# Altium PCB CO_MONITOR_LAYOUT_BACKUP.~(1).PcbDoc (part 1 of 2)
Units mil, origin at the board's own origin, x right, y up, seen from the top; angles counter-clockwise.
Board outline 3010 x 4260 mil, 2 copper layers (Top Layer, Bottom Layer), stack 62 mil thick; 120 components, 0 nets, 435 pads, 123 vias.
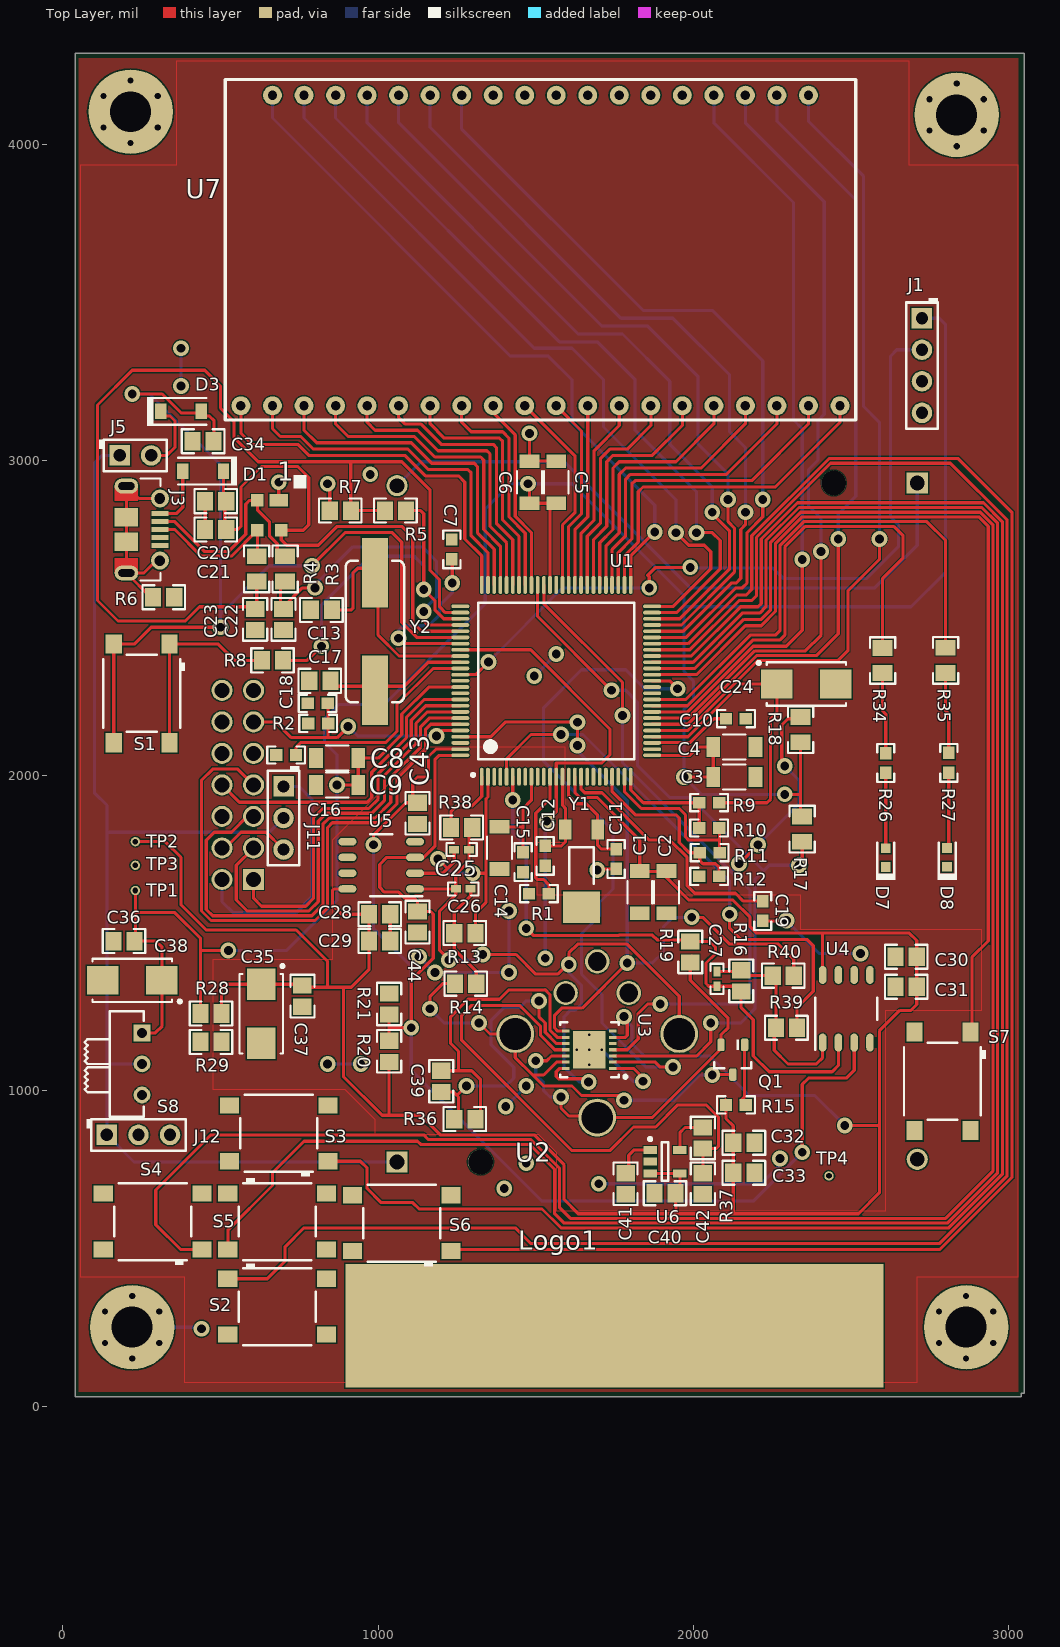
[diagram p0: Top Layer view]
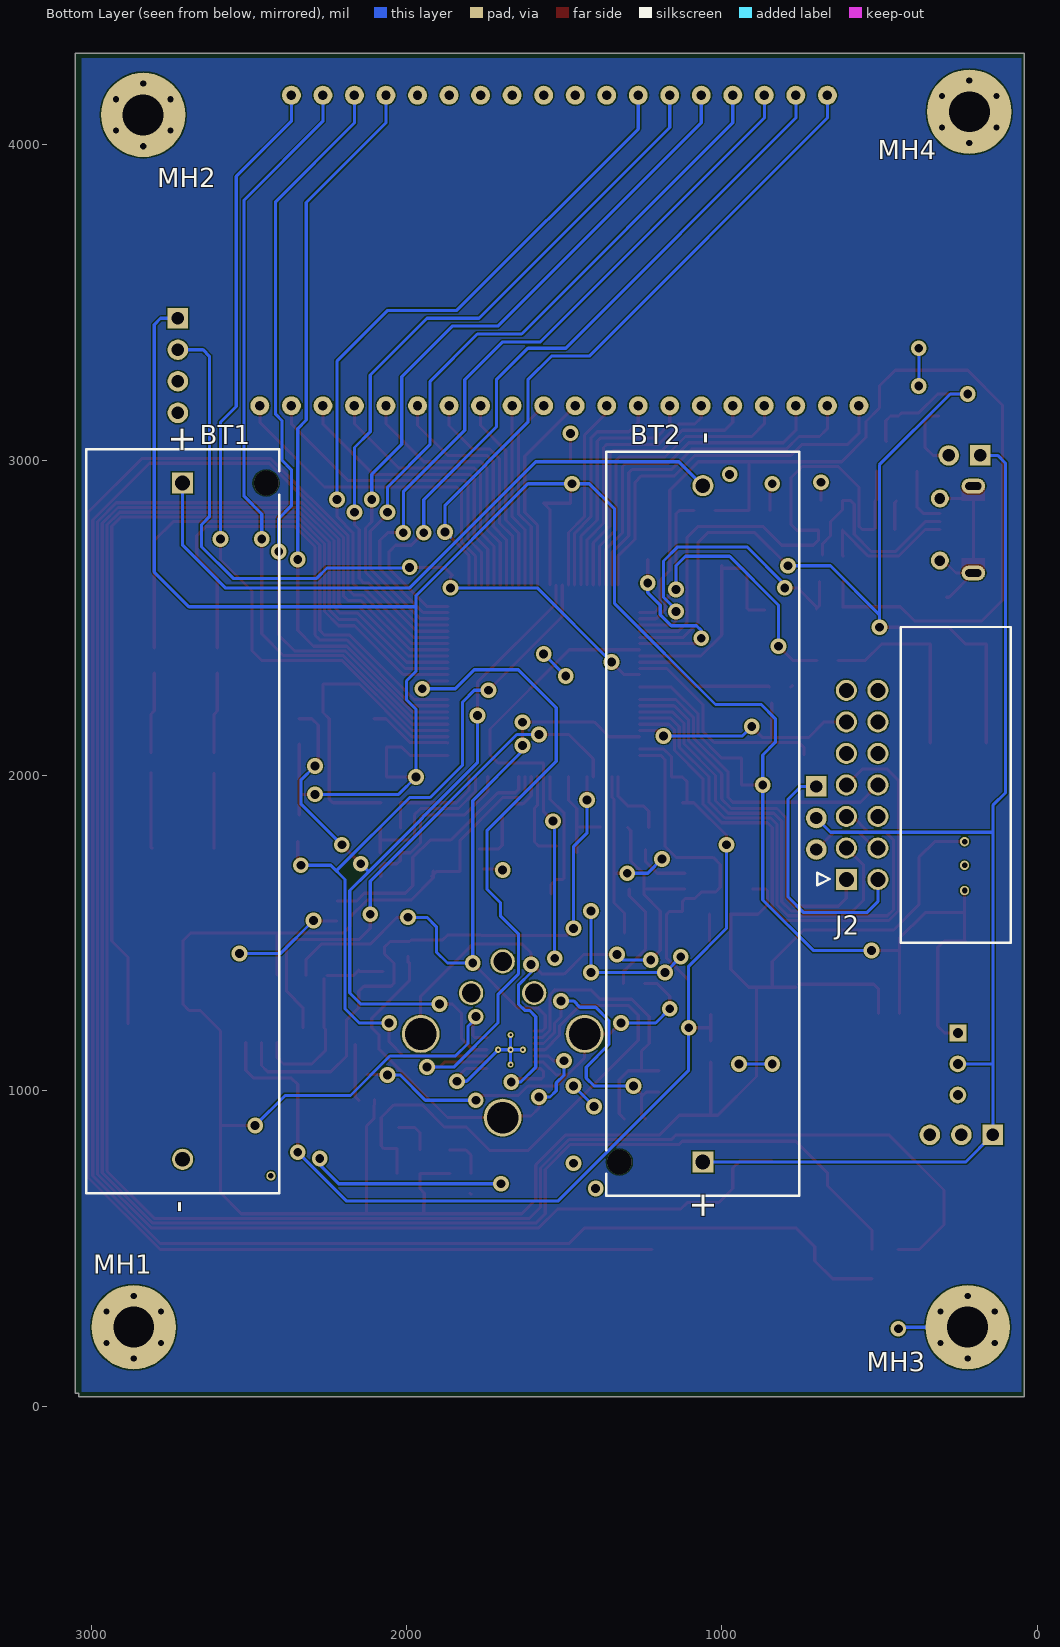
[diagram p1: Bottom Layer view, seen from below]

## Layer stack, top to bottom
Top Solder: solder mask 0.4, Solder Resist, Dk 3.5
Top Layer: signal copper 1.4
Dielectric1: core 59.2, FR-4, Dk 4.8
Bottom Layer: signal copper 1.4
Bottom Solder: solder mask 0.4, Solder Resist, Dk 3.5

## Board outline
40,30 40,4290 110,4290 3050,4290 3050,4250 3050,40 3040,40 3040,30 40,30

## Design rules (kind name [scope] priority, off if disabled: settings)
Clearance Clearance_Power_Polugone [(InPolygon AND InNetClass('All Nets'))] p1: gap=5
Clearance [All] p2: gap=4
HoleSize [All] p1: absolutevalues=TRUE maxlimit=240 minlimit=5 maxpercent=80.000 minpercent=20.000
MinimumAnnularRing [All] p1: minimumring=5
MinimumSolderMaskSliver [All] p1: minsoldermaskwidth=2
PlaneConnect [All] p1: planeconnectstyle=Relief reliefexpansion=20 reliefentries=4 reliefconductorwidth=10 reliefairgap=50
PolygonConnect [All] p1: connectstyle=Relief reliefconductorwidth=10 reliefentries=4 polygonreliefangle="90 Angle" airgapwidth=10
RoutingVias [All] p1: holewidth=28 width=50 viastyle="Through Hole" minholewidth=28 minwidth=50 maxholewidth=28 maxwidth=50
SilkToBoardRegionClearance [Not ((IsComment or IsDesignator) And (Hide <> 'False')) and not InRegion(1000,500,4000,800)] p1:
SilkToSilkClearance [All] p1: silktosilkclearance=5
SilkToSolderMaskClearance [IsPad] p1: minsilkscreentomaskgap=5 clearancetoexposedcopper=TRUE
SolderMaskExpansion [All] p1: expansion=0
Width [All] p1: maxlimit=10 minlimit=10 preferedwidth=10
24 further rules are at their usual default settings.

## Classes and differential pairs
component class EVM_Hardware: ZZ1 ZZ2 ZZ3 ZZ4
component class AssemblyNote: ZZ1 ZZ2 ZZ3 ZZ4

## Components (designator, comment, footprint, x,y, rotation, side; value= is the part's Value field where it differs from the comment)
1 "TPD2E001DZDR" DZD 655,2825 r180 top
BT1 "1015" Keystone_1015 2710,1855 r270 bottom
BT2 "1015" Keystone_1015 1060,1846.54 r90 bottom
C1 "C3216NP01H104J160AA" 1206_190 1830,1630 r270 top
C2 "C3216NP01H104J160AA" 1206_190 1915,1630 r270 top
C3 "C3216NP01H104J160AA" 1206_190 2130,1995 r0 top
C4 "C3216NP01H104J160AA" 1206_190 2130,2090 r0 top
C5 "C3216NP01H104J160AA" 1206_190 1565,2930 r90 top
C6 "C3216NP01H104J160AA" 1206_190 1480,2930 r90 top
C7 "C1608X7R1H224K080AB" 0603 1233.83,2716.94 r90 top
C8 "C3216NP01H104J160AA" 1206_190 870,2055 r180 top
C9 "C3216NP01H104J160AA" 1206_190 870,1970 r180 top
C10 "GRM188R61C474KA93D" 0603 2135,2180 r0 top
C11 "C1608C0G1H120J" 0603 1755,1735 r90 top
C12 "C1608C0G1H120J" 0603 1530,1745 r90 top
C13 "C0805C180J5GACTU" 0805 820,2525 r180 top
C14 "C3216NP01H104J160AA" 1206_190 1385,1770 r270 top
C15 "GRM188R60J106ME84" 0603 1460,1725 r270 top
C16 "C0603C472J5RACTU" 0603 708.19,2065 r0 top
C17 "C0805C180J5GACTU" 0805 815,2300 r180 top
C18 "GRM188R71C222KA01D" 0603 808.19,2228.83 r180 top
C19 "GRM188R71H223KA01D" 0603 2220,1570 r90 top
C20 "GRM21BC81E475KA12L" 0805 485,2870 r180 top
C21 "GRM21BR71H104KA01L" 0805 485,2780 r180 top
C22 "08055A100JAT2A" 0805 700,2495 r270 top
C23 "08055A100JAT2A" 0805 610,2495 r270 top
C24 "293D475X9025C2TE3" 6032-28 2358.31,2290 r0 top
C25 "500R07S0R3BV4T" 0402 1265,1765 r0 top
C26 "500R07S0R3BV4T" 0402 1270,1640 r180 top
C27 "500R07S0R3BV4T" 0402 2074.84,1355 r90 top
C28 "08055C104JAT2A" 0805 1005,1560 r0 top
C29 "08055C104JAT2A" 0805 1005,1475 r0 top
C30 "08055C104JAT2A" 0805 2675,1425 r180 top
C31 "08055C104JAT2A" 0805 2675,1330 r180 top
C32 "08055C104JAT2A" 0805 2160,835 r0 top
C33 "08055C104JAT2A" 0805 2160,740 r0 top
C34 "GRM219R71E224KA01D" 0805 445,3060 r180 top
C35 "293D106X9020C2TE3" 6032-28 629.65,1244.18 r270 top
C36 "C0805C104K4RACTU" 0805 194.18,1474.68 r180 top
C37 "C0805C104K4RACTU" 0805 760,1300 r270 top
C38 "293D106X9020C2TE3" 6032-28 220,1350 r180 top
C39 "C0805C105K4RACTU" 0805 1200,1030 r90 top
C40 "08055C104JAT2A" 0805 1910,675 r180 top
C41 "08055A560JAT2A" 0805 1785,705 r270 top
C42 "08055C223KAT2A" 0805 2030,705 r270 top
C43 "08055C104JAT2A" 0805 1125,1880 r270 top
C44 "08055C104JAT2A" 0805 1125,1535 r270 top
D1 "SD103AW-7-F" SOD-123 445,2965 r180 top
D3 "SD103AW-7-F" SOD-123 375,3155 r0 top
D7 "19-21SURC/S530-A3/TR8" 19-21_Red 2610,1739.53 r90 top
D8 "19-21SURC/S530-A3/TR8" 19-21_Red 2805,1740 r90 top
J1 "5-146278-4" TE_5-146278-4 2725,3300 r270 top
J2 "612 014 217 21" WURTH_612_014_217_21 555,1970 r90 bottom
J3 "105017-0001" CONN_105017-0001 255,2780 r270 top
J5 "5-146278-2" TE_5-146278-2 230,3015 r0 top
J11 "5-146278-3" TE_5-146278-3 700,1865 r270 top
J12 "5-146278-3" TE_5-146278-3 240,860 r0 top
Logo1 "Texas Instruments" TI_Stacked_SolderMask_Medium 1750,255 r0 top
MH1 "MTG_Pads" MTGP_M3_PanHead 2865,250 r0 bottom
MH2 "MTG_Pads" MTGP_M3_PanHead 2835,4095 r0 bottom
MH3 "MTG_Pads" MTGP_M3_PanHead 220,250 r0 bottom
MH4 "MTG_Pads" MTGP_M3_PanHead 215,4105 r0 bottom
Q1 "BSH201,215" SOT-23 2125,1098.46 r270 top
R1 "CRCW06030000Z0EA" 0603 1510,1625 r0 top
R2 "RT0603BRD0747KL" 0603 810,2165 r180 top
R3 "CRCW080527R0JNEA" 0805_HV 705,2655 r270 top
R4 "CRCW080527R0JNEA" 0805_HV 615,2655 r270 top
R5 "CRCW08051K40FKEA" 0805 1055,2840 r0 top
R6 "CRCW080533K0JNEA" 0805 320,2565 r180 top
R7 "CRCW08051M00JNEA" 0805 880,2840 r0 top
R8 "RT0805BRD07100RL" 0805 665,2365 r180 top
R9 "CRCW06030000Z0EA" 0603 2050,1913.5 r0 top
R10 "CRCW06030000Z0EA" 0603 2050,1833.5 r180 top
R11 "CRCW06030000Z0EA" 0603 2051.5,1755 r0 top
R12 "CRCW06030000Z0EA" 0603 2050,1680 r0 top
R13 "RG2012P-103-B-T5" 0805 1275,1500 r0 top
R14 "RG2012P-103-B-T5" 0805 1277.75,1339.65 r0 top
R15 "CRCW060310K0FKEA" 0603 2135,955 r180 top
R16 "RG2012P-103-B-T5" 0805 2151.5,1348.5 r270 top
R17 "RG2012P-332-B-T5" 0805_HV 2345,1830 r270 top
R18 "RG2012P-332-B-T5" 0805_HV 2340,2145 r90 top
R19 "ERJ-6GEYJ102V" 0805 1990,1440 r90 top
R20 "RG2012P-103-B-T5" 0805 1035,1125 r270 top
R21 "RG2012P-103-B-T5" 0805 1035,1275 r270 top
R26 "CRCW0603470RJNEA" 0603 2610,2039.53 r270 top
R27 "CRCW0603470RJNEA" 0603 2810,2040 r270 top
R28 "CRCW08050000Z0EA" 0805 470,1245 r0 top
R29 "CRCW08050000Z0EA" 0805 470,1155 r0 top
R34 "MCR10EZPJ000" 0805_HV 2600,2364.53 r270 top
R35 "MCR10EZPJ000" 0805_HV 2800,2365 r270 top
R36 "CRCW08051K10JNEA" 0805 1275,910 r180 top
R37 "CRCW08050000Z0EA" 0805 2030,850 r270 top
R38 "CRCW08050000Z0EA" 0805 1265,1835 r0 top
R39 "CRCW08050000Z0EA" 0805 2295,1200 r0 top
R40 "CRCW08050000Z0EA" 0805 2285,1365 r0 top
S1 "430182080816" SW_430182080816 250,2260 r270 top
S2 "430182080816" SW_430182080816 680,315 r0 top
S3 "430182080816" SW_430182080816 685,865 r180 top
S4 "430182080816" SW_430182080816 285,585 r180 top
S5 "430182080816" SW_430182080816 680,585 r0 top
S6 "430182080816" SW_430182080816 1075,580 r180 top
S7 "430182080816" SW_430182080816 2790,1030 r270 top
S8 "MHSS1105" SW_MHSS1105 200,1085 r270 top
TP1 "TESTPOINT" TP_H045P075 230,1635 r270 top
TP2 "TESTPOINT" TP_H045P075 230,1790 r90 top
TP3 "TESTPOINT" TP_H045P075 230,1715 r270 top
TP4 "TESTPOINT" TP_H045P075 2430,730 r90 top
U1 "MSP430FG6626IPZR" PZ0100A_N 1565,2300 r90 top
U2 "CO_AF" CO_AF 1695,1180 r180 top
U3 "LMP91000_NHL_14" SDA14B 1670,1130 r180 top
U4 "LMC6442AIM" D0008A_N 2485,1260 r90 top
U5 "LMC6442AIM" D0008A_N 1010,1715 r180 top
U6 "LM4120AIM5-2.5/NOPB" MF05A_N 1910,775 r0 top
U7 "FH1138P" FH1138P 1515,3665 r0 top
Y1 "MS1V-T1K 32.768KHZ +-20PPM 12.5PF" XTAL_MS1V-T1K 1645,1705 r270 top
Y2 "ABLS2-4.000MHZ-D4Y-T" ABRACON_ABLS2 989.8,2456.54 r90 top
ZZ1 "This Assembly Note is for PCB labels only" AssemblyNoteLabel 95,7618 r0 top
ZZ2 "These assemblies are ESD sensitive, ESD precautions shall be observed." AssemblyNote 95,7509.11 r0 top
ZZ3 "These assemblies must be clean and free from flux and all contaminants. Use of no clean flux is not acceptable." AssemblyNote 95,7420.56 r0 top
ZZ4 "These assemblies must comply with workmanship standards IPC-A-610 Class 2, unless otherwise specified." AssemblyNote 95,7332 r0 top

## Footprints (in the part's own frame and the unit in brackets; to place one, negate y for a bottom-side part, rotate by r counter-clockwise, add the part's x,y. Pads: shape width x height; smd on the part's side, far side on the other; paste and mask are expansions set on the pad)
19-21_Red [mm] "SMD, 2-Leads, Body 0.8x1.6mm, Pin Spacing 1.5mm"
  rect 0.8x0.8 smd: 1(-0.75,0) 2(0.75,0)
  silkscreen extent -1.8,-0.8 1.2,0.8, body extent -0.9,-0.45 0.9,0.45, height 1.01
0402 [mm] "0402 from SM-752 data"
  rect 0.8x0.6 smd: 1(-0.6,0) 2(0.6,0)
  silkscreen extent -1.22,-0.52 1.22,0.52, body extent -0.55,-0.3 0.55,0.3, height 0.6
0603 [mm] "0603 from SM-752 data"
  rect 1x0.95 smd: 1(-0.8,0) 2(0.8,0)
  silkscreen extent -1.52,-0.69 1.52,0.69, body extent -0.87,-0.47 0.87,0.47, height 0.85
0805 [mm] "0805 from SM-752 data"
  rect 1.3x1.5 smd: 1(-0.85,0) 2(0.85,0)
  silkscreen extent -1.72,-0.97 1.72,0.97, body extent -1.1,-0.72 1.1,0.72, height 1.45
0805_HV [mil] "0805 with 30mil clearance between pads"
  rect 50x63 smd: 1(-40,0) 2(40,0)
  silkscreen extent -74,-40 74,40, body extent -43,-29 43,29, height 57
1206_190 [mm] "1206_190"
  rect 1.1x1.6 smd: 1(-1.7,0) 2(1.7,0)
  silkscreen extent -0.9,-1 0.9,1, body extent -1.75,-0.95 1.75,0.95, height 1.9
6032-28 [mm] "Medium Density IPC based on Vishay Sprague 293D datasheet."
  rect 2.55x2.3 smd: 1(-2.375,0) 2(2.375,0)
  silkscreen extent -3.96,-1.75 3.2,1.82, body extent -3.15,-1.75 3.15,1.75, height 2.8
ABRACON_ABLS2 [mm] "SMD, 2-Leads, Body 11.4x4.7mm"
  rect 5.6x2.1 smd: 1(-4.75,0) 2(4.75,0)
  silkscreen extent -5.71,-2.35 5.72,2.35, body extent -6.35,-2.35 6.35,2.35, height 3.27
AssemblyNote [mil] "Assembly Note"
AssemblyNoteLabel [mil] "Assembly Note for PCB Labels"
CO_AF [mil]
  round 120 hole 100: 1(-260,0) 2(260,0) 3(0,265)
  round 76.93 hole 59.06: 7(0,-230) 8(100,-130) 9(-100,-130)
  body extent -347,-324 359,384, height 690
CONN_105017-0001 [mm] "Molex Micro USB-B"
  rect 0.4x1.35 smd mask+0.051: 1(-1.3,1.35) 2(-0.65,1.35) 3(0,1.35) 4(0.65,1.35) 5(1.3,1.35)
  oval 1.2x1.9 hole 0.6 slot 1.3 at 90 deg: 6(-3.5,-1.35) 9(3.5,-1.35)
  rect 1.5x1.9 smd: 7(-1,-1.35) 8(1,-1.35)
  round 1.45 hole 0.85: 10(2.5,1.35) 11(-2.5,1.35)
  Top Layer region: 3.5,-0.4 2.3,-0.4 2.3,-2.3 3.5,-2.3
  Top Layer region: -3.5,-2.3 -2.3,-2.3 -2.3,-0.4 -3.5,-0.4
  silkscreen extent -4.1,-0.2 4.1,1.4, body extent -4.1,-3.93 4.1,1.5, height 2.72
D0008A_N [mm] "SOIC, 8-Leads, Body 4.9x3.9mm, Pitch 1.27mm, IPC Medium Density"
  oval 1.45x0.6 smd: 1(-2.725,1.905) 2(-2.725,0.635) 3(-2.725,-0.635) 4(-2.725,-1.905) 5(2.725,-1.905) 6(2.725,-0.635) 7(2.725,0.635) 8(2.725,1.905)
  silkscreen extent -3.3,-2.5 0.9,2.5, body extent -3,-2.45 3,2.45, height 1.63
DZD [mm]
  rect 1.5x1 smd: 1(-0.76,-1.2)
  rect 1x1 smd mask+0.05: 2(0.96,-1.2) 3(0.96,1.2) 4(-0.96,1.2)
  silkscreen extent -2.99,-3.21 -1.97,-2.19
FH1138P [mil]
  round 60 hole 30: 1(-950,-492.5) 2(-850,-492.5) 3(-750,-492.5) 4(-650,-492.5) 5(-550,-492.5) 6(-450,-492.5) 7(-350,-492.5) 8(-250,-492.5) 9(-150,-492.5) 10(-50,-492.5) 11(50,-492.5) 12(150,-492.5) 13(250,-492.5) 14(350,-492.5) 15(450,-492.5) 16(550,-492.5) 17(650,-492.5) 18(750,-492.5) 19(850,-492.5) 20(950,-492.5) 21(850,492.5) 22(750,492.5) 23(650,492.5) 24(550,492.5) 25(450,492.5) 26(350,492.5) 27(250,492.5) 28(150,492.5) 29(50,492.5) 30(-50,492.5) 31(-150,492.5) 32(-250,492.5) 33(-350,492.5) 34(-450,492.5) 35(-550,492.5) 36(-650,492.5) 37(-750,492.5) 38(-850,492.5)
  silkscreen extent -1000,-538 1000,542, body extent -1080,-501 1085,511, height 202
Keystone_1015 [mm] "AA Battery Holder, Through-hole mount"
  rect 1.7x1.7 hole 1.19: 1(-27.24,0)
  round 1.7 hole 1.19: 2(27.24,0)
  round 1.98 hole 1.98 unplated paste+0 mask+0: MH1(-27.24,6.73)
  silkscreen extent -29.97,-7.77 29.97,7.77, body extent -30,-7.74 29.93,7.8, height 14.86
MF05A_N [mm] "SOT23, 5-Leads, Body 2.9x1.6mm, Pitch 0.95mm, Lead Span 2.8mm, IPC Medium Density"
  rect 1.1x0.65 smd: 1(-1.2,0.95) 2(-1.2,0) 3(-1.2,-0.95) 4(1.2,-0.95) 5(1.2,0.95)
  silkscreen extent -1.32,-1.55 0.25,1.95, body extent -0.9,-1.55 0.9,1.55, height 1.19
MTGP_M3_PanHead [mm] "M3Mounting Hole, Plated, for Pan Head"
  round 6.8 hole 3.3: 1(0,0)
PZ0100A_N [mm] "TSQFP, 100-Leads, Body 16.2x16.2mm (max), Pitch 0.50mm, IPC Medium Density"
  oval 1.45x0.3 smd: 1(-7.725,6) 2(-7.725,5.5) 3(-7.725,5) 4(-7.725,4.5) 5(-7.725,4) 6(-7.725,3.5) 7(-7.725,3) 8(-7.725,2.5) 9(-7.725,2) 10(-7.725,1.5) 11(-7.725,1) 12(-7.725,0.5) 13(-7.725,0) 14(-7.725,-0.5) 15(-7.725,-1) 16(-7.725,-1.5) 17(-7.725,-2) 18(-7.725,-2.5) 19(-7.725,-3) 20(-7.725,-3.5) 21(-7.725,-4) 22(-7.725,-4.5) 23(-7.725,-5) 24(-7.725,-5.5) 25(-7.725,-6) 51(7.725,-6) 52(7.725,-5.5) 53(7.725,-5) 54(7.725,-4.5) 55(7.725,-4) 56(7.725,-3.5) 57(7.725,-3) 58(7.725,-2.5) 59(7.725,-2) 60(7.725,-1.5) 61(7.725,-1) 62(7.725,-0.5) 63(7.725,0) 64(7.725,0.5) 65(7.725,1) 66(7.725,1.5) 67(7.725,2) 68(7.725,2.5) 69(7.725,3) 70(7.725,3.5) 71(7.725,4) 72(7.725,4.5) 73(7.725,5) 74(7.725,5.5) 75(7.725,6)
  oval 0.3x1.45 smd: 26(-6,-7.725) 27(-5.5,-7.725) 28(-5,-7.725) 29(-4.5,-7.725) 30(-4,-7.725) 31(-3.5,-7.725) 32(-3,-7.725) 33(-2.5,-7.725) 34(-2,-7.725) 35(-1.5,-7.725) 36(-1,-7.725) 37(-0.5,-7.725) 38(0,-7.725) 39(0.5,-7.725) 40(1,-7.725) 41(1.5,-7.725) 42(2,-7.725) 43(2.5,-7.725) 44(3,-7.725) 45(3.5,-7.725) 46(4,-7.725) 47(4.5,-7.725) 48(5,-7.725) 49(5.5,-7.725) 50(6,-7.725) 76(6,7.725) 77(5.5,7.725) 78(5,7.725) 79(4.5,7.725) 80(4,7.725) 81(3.5,7.725) 82(3,7.725) 83(2.5,7.725) 84(2,7.725) 85(1.5,7.725) 86(1,7.725) 87(0.5,7.725) 88(0,7.725) 89(-0.5,7.725) 90(-1,7.725) 91(-1.5,7.725) 92(-2,7.725) 93(-2.5,7.725) 94(-3,7.725) 95(-3.5,7.725) 96(-4,7.725) 97(-4.5,7.725) 98(-5,7.725) 99(-5.5,7.725) 100(-6,7.725)
  silkscreen extent -7.7,-6.3 6.3,6.82, body extent -8.01,-8.01 8.01,8.01, height 1.6
SDA14B [mm] "SON, 14-Leads, Body 4x4mm, Pitch 0.5mm, NSC Recommended"
  rect 0.6x0.25 smd paste-0.125 mask+0.051: 1(-1.9,1.5) 2(-1.9,1) 3(-1.9,0.5) 4(-1.9,0) 5(-1.9,-0.5) 6(-1.9,-1) 7(-1.9,-1.5) 8(1.9,-1.5) 9(1.9,-1) 10(1.9,-0.5) 11(1.9,0) 12(1.9,0.5) 13(1.9,1) 14(1.9,1.5)
  rect 2.6x3 smd paste-1.3 mask+0.051: 15(0,0)
  silkscreen extent -3.03,-2.2 2.35,2.3, body extent -2.05,-2.05 2.05,2.05, height 0.8
SOD-123 [mm] "On Semi recommended land pattern"
  rect 0.915x1.22 smd: 1(-1.637,0) 2(1.637,0)
  silkscreen extent -2.74,-1.17 2.03,1.17, body extent -1.93,-0.9 1.93,0.9, height 1.35
SOT-23 [mm] "SOT23, 3-Leads, Body 2.9x1.3mm, Pitch 0.95mm, Lead Span 2.5mm, IPC Medium Density"
  rrect50% 1x0.6 smd: 1(-1.2,0.95) 2(-1.2,-0.95) 3(1.2,0)
  silkscreen extent -1.63,-1.5 0.7,1.5, body extent -1.16,-1.45 1.21,1.45, height 1
SW_430182080816 [mm] "SMD, 4-Leads, Body 6.2x6.2mm"
  rect 1.55x1.3 smd: 1(-3.975,2.25) 2(-3.975,-2.25) 3(3.975,2.25) 4(3.975,-2.25)
  silkscreen extent -3.1,-3.1 3.1,3.5, body extent -4.5,-3.1 4.5,3.1, height 8
SW_MHSS1105 [mm] "APEM"
  rect 1.35x1.35 hole 0.8: 1(-2.5,1.3)
  round 1.35 hole 0.8: 2(0,1.3) 3(2.5,1.3)
  silkscreen extent -4.25,-3.31 4.26,1.45, body extent -4.25,-3.3 4.25,2.21, height 5.06
TE_5-146278-2 [mm] "TE CONNECTIVITY"
  rect 1.65x1.65 hole 1: 1(-1.27,0)
  round 1.65 hole 1: 2(1.27,0)
  silkscreen extent -2.92,-1.27 2.54,1.27, body extent -2.41,-1.17 2.41,1.17, height 8.13
TE_5-146278-3 [mm] "TE CONNECTIVITY"
  rect 1.65x1.65 hole 1: 1(-2.54,0)
  round 1.65 hole 1: 2(0,0) 3(2.54,0)
  silkscreen extent -4.19,-1.27 3.81,1.27, body extent -3.68,-1.17 3.68,1.17, height 8.13
TE_5-146278-4 [mm] "TE CONNECTIVITY"
  rect 1.65x1.65 hole 1: 1(-3.81,0)
  round 1.65 hole 1: 2(-1.27,0) 3(1.27,0) 4(3.81,0)
  silkscreen extent -5.46,-1.27 5.08,1.27, body extent -4.95,-1.17 4.95,1.17, height 8.13
TI_Stacked_SolderMask_Medium [mil]
  rect 1706x392 smd paste-196 mask-196: 0(0,0)
TP_H045P075 [mm] "TP_H0.45P0.75"
  round 0.75 hole 0.45: 1(0,0)
WURTH_612_014_217_21 [mm] "Header, 2.54 mm, 7x2, R/A, TH"
  rect 1.7x1.7 hole 1.2: 1(-7.62,1.27)
  round 1.7 hole 1.2: 2(-7.62,-1.27) 3(-5.08,1.27) 4(-5.08,-1.27) 5(-2.54,1.27) 6(-2.54,-1.27) 7(0,1.27) 8(0,-1.27) 9(2.54,1.27) 10(2.54,-1.27) 11(5.08,1.27) 12(5.08,-1.27) 13(7.62,1.27) 14(7.62,-1.27)
  silkscreen extent -12.72,-11.96 12.72,3.6, body extent -12.72,-11.96 12.72,1.59, height 9.1
XTAL_MS1V-T1K [mm] "SMD, 3-Leads, Body 2.0x8.1x2.0mm"
  rect 1.6x1 smd: 1(-3.125,1.3) 2(-3.125,-1.3)
  rect 2.5x3 smd: 3(3.125,0)
  silkscreen extent -1.73,-1 1.25,1, body extent -3.72,-1.38 4.38,1.38, height 2.08

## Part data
1: "IC, Low-Capacitacnce 2-Chan ±15-kV ESD-Protection Array"
BT1 BT2: "AA Battery Holder, Through-hole mount"
C1 C2 C3 C4 C5 C6 C8 C9 C14: "CAP, CERM, 0.1 µF, 50 V, +/- 5%, C0G/NP0, 1206_190"
C7: "CAP, CERM, 0.22 µF, 50 V, +/- 10%, X7R, 0603"
C10: "CAP, CERM, 0.47 µF, 16 V, +/- 10%, X5R, 0603"
C11 C12: "CAP, CERM, 12 pF, 50 V, +/- 5%, C0G/NP0, 0603"
C13 C17: "CAP, CERM, 18 pF, 50 V, +/- 5%, C0G/NP0, 0805"
C15: "CAP, CERM, 10 µF, 6.3 V, +/- 20%, X5R, 0603"
C16: "CAP, CERM, 4700 pF, 50 V, +/- 5%, X7R, 0603"
C18: "CAP, CERM, 2200 pF, 16 V, +/- 10%, X7R, 0603"
C19: "CAP, CERM, 0.022 µF, 50 V, +/- 10%, X7R, 0603"
C20: "CAP, CERM, 4.7 µF, 25 V, +/- 10%, X6S, 0805"
C21: "CAP, CERM, 0.1 µF, 50 V, +/- 10%, X7R, 0805"
C22 C23: "CAP, CERM, 10 pF, 50 V, +/- 5%, C0G/NP0, 0805"
C24: "CAP, TA, 4.7 µF, 25 V, +/- 10%, 2 ohm, SMD"
C25 C26 C27: "CAP, CERM, 0.3 pF, 50 V, +/- 30%, C0G/NP0, 0402"
C28 C29 C30 C31 C32 C33 C40 C43 C44: "CAP, CERM, 0.1 µF, 50 V, +/- 5%, X7R, 0805"
C34: "CAP, CERM, 0.22 µF, 25 V, +/- 10%, X7R, 0805"
C35 C38: "CAP, TA, 10 µF, 20 V, +/- 10%, 1.7 ohm, SMD"
C36 C37: "CAP, CERM, 0.1 µF, 16 V, +/- 10%, X7R, 0805"
C39: "CAP, CERM, 1 µF, 16 V, +/- 10%, X7R, 0805"
C41: "CAP, CERM, 56 pF, 50 V, +/- 5%, C0G/NP0, 0805"
C42: "CAP, CERM, 0.022 µF, 50 V, +/- 10%, X7R, 0805"
D1 D3: "Diode, Schottky, 40 V, 0.35 A, SOD-123"
D7 D8: "LED, Red, SMD"
J1: "Header, 100mil, 4x1, Tin, TH"
J2: "Header (Shrouded), 2.54 mm, 7x2, Gold, R/A, TH"
J3: "Connector, Receptacle, Micro-USB Type B, R/A, Bottom Mount SMT"
J5: "Header, 100mil, 2x1, Tin, TH"
J11 J12: "Header, 100mil, 3x1, Tin, TH"
Logo1: library part TI_Logo, "Texas Instrument Corporate Signature"
MH1 MH2 MH3 MH4: library part "Mounting Hole (Metric) with Pads", "PCB Mounting Hole"
Q1: "MOSFET, P-CH, -60 V, -0.3 A, SOT-23"
R1 R9 R10 R11 R12: "RES, 0, 5%, 0.1 W, 0603"
R2: "RES, 47.0 k, 0.1%, 0.1 W, 0603"
R3 R4: "RES, 27, 5%, 0.125 W, 0805"
R5: "RES, 1.40 k, 1%, 0.125 W, 0805"
R6: "RES, 33 k, 5%, 0.125 W, 0805"
R7: "RES, 1.0 M, 5%, 0.125 W, 0805"
R8: "RES, 100, 0.1%, 0.125 W, 0805"
R13 R14 R16 R20 R21: "RES, 10.0 k, 0.1%, 0.125 W, 0805"
R15: "RES, 10.0 k, 1%, 0.1 W, 0603"
R17 R18: "RES, 3.30 k, 0.1%, 0.125 W, 0805"
R19: "RES, 1.0 k, 5%, 0.125 W, 0805"
R26 R27: "RES, 470, 5%, 0.1 W, 0603"
R28 R29 R34 R35 R37 R38 R39 R40: "RES, 0, 5%, 0.125 W, 0805"
R36: "RES, 1.1 k, 5%, 0.125 W, 0805"
S1 S2 S3 S4 S5 S6 S7: "Switch, Tactile, SPST-NO, 0.05A, 12V, SMD"
S8: "Switch, Slide, SPDT, R/A, TH"
TP1 TP2 TP3 TP4: library part TP_H0.45P0.75, "Testpoint"
U1: "Mixed-Signal Microcontrollers, PZ0100A"
U3: "Imported"
U4 U5: "Dual Micropower Rail-to-Rail Output Operational Amplifier, D0008A"
U6: "Precision Micropower Low Dropout Voltage Reference, 5-pin SOT-23, Pb-Free"
Y1: "Tuning Fork Crystal, 32.768 kHz, 12.5 pF, SMD"
Y2: "Crystal, 4MHz, 18pF, SMD"
ZZ1: library part AssemblyNoteLabel
ZZ2 ZZ3 ZZ4: library part AssemblyNote

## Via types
v1: diameter 50, hole 28, Top Layer to Bottom Layer, 65 vias
v2: diameter 50, hole 28, Top Layer to Bottom Layer, tented top, 29 vias
v3: diameter 39.37, hole 19.68, Top Layer to Bottom Layer, 24 vias
v4: diameter 19.68, hole 7.87, Top Layer to Bottom Layer, tented top, 5 vias

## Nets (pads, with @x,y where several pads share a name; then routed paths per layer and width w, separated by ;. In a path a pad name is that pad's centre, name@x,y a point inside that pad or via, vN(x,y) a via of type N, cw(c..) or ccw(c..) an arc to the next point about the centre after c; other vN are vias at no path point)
pads on no net: 1.1 1.2 1.3 1.4 BT1.1 BT1.2 BT1.MH1 BT2.1 BT2.2 BT2.MH1 C1.1 C1.2 C2.1 C2.2 C3.1 C3.2 C4.1 C4.2 C5.1 C5.2 C6.1 C6.2 C7.1 C7.2 C8.1 C8.2 C9.1 C9.2 C10.1 C10.2 C11.1 C11.2 C12.1 C12.2 C13.1 C13.2 C14.1 C14.2 C15.1 C15.2 C16.1 C16.2 C17.1 C17.2 C18.1 C18.2 C19.1 C19.2 C20.1 C20.2 C21.1 C21.2 C22.1 C22.2 C23.1 C23.2 C24.1 C24.2 C25.1 C25.2 C26.1 C26.2 C27.1 C27.2 C28.1 C28.2 C29.1 C29.2 C30.1 C30.2 C31.1 C31.2 C32.1 C32.2 C33.1 C33.2 C34.1 C34.2 C35.1 C35.2 C36.1 C36.2 C37.1 C37.2 C38.1 C38.2 C39.1 C39.2 C40.1 C40.2 C41.1 C41.2 C42.1 C42.2 C43.1 C43.2 C44.1 C44.2 D1.1 D1.2 D3.1 D3.2 D7.1 D7.2 D8.1 D8.2 J1.1 J1.2 J1.3 J1.4 J2.1 J2.2 J2.3 J2.4 J2.5 J2.6 J2.7 J2.8 J2.9 J2.10 J2.11 J2.12 J2.13 J2.14 J3.1 J3.2 J3.3 J3.4 J3.5 J3.6 J3.7 J3.8 J3.9 J3.10 J3.11 J5.1 J5.2 J11.1 J11.2 J11.3 J12.1 J12.2 J12.3 Logo1.0 MH1.1 MH2.1 MH3.1 MH4.1 Q1.1 Q1.2 Q1.3 R1.1 R1.2 R2.1 R2.2 R3.1 R3.2 R4.1 R4.2 R5.1 R5.2 R6.1 R6.2 R7.1 R7.2 R8.1 R8.2 R9.1 R9.2 R10.1 R10.2 R11.1 R11.2 R12.1 R12.2 R13.1 R13.2 R14.1 R14.2 R15.1 R15.2 R16.1 R16.2 R17.1 R17.2 R18.1 R18.2 R19.1 R19.2 R20.1 R20.2 R21.1 R21.2 R26.1 R26.2 R27.1 R27.2 R28.1 R28.2 R29.1 R29.2 R34.1 R34.2 R35.1 R35.2 R36.1 R36.2 R37.1 R37.2 R38.1 R38.2 R39.1 R39.2 R40.1 R40.2 S1.1 S1.2 S1.3 S1.4 S2.1 S2.2 S2.3 S2.4 S3.1 S3.2 S3.3 S3.4 S4.1 S4.2 S4.3 S4.4 S5.1 S5.2 S5.3 S5.4 S6.1 S6.2 S6.3 S6.4 S7.1 S7.2 S7.3 S7.4 S8.1 S8.2 S8.3 TP1.1 TP2.1 TP3.1 TP4.1 U1.1 U1.2 U1.3 U1.4 U1.5 U1.6 U1.7 U1.8 U1.9 U1.10 U1.11 U1.12 U1.13 U1.14 U1.15 U1.16 U1.17 U1.18 U1.19 U1.20 U1.21 U1.22 U1.23 U1.24 U1.25 U1.26 U1.27 U1.28 U1.29 U1.30 U1.31 U1.32 U1.33 U1.34 U1.35 U1.36 U1.37 U1.38 U1.39 U1.40 U1.41 U1.42 U1.43 U1.44 U1.45 U1.46 U1.47 U1.48 U1.49 U1.50 U1.51 U1.52 U1.53 U1.54 U1.55 U1.56 U1.57 U1.58 U1.59 U1.60 U1.61 U1.62 U1.63 U1.64 U1.65 U1.66 U1.67 U1.68 U1.69 U1.70 U1.71 U1.72 U1.73 U1.74 U1.75 U1.76 U1.77 U1.78 U1.79 U1.80 U1.81 U1.82 U1.83 U1.84 U1.85 U1.86 U1.87 U1.88 U1.89 U1.90 U1.91 U1.92 U1.93 U1.94 U1.95 U1.96 U1.97 U1.98 U1.99 U1.100 U2.1 U2.2 U2.3 U2.7 U2.8 U2.9 U3.1 U3.2 U3.3 U3.4 U3.5 U3.6 U3.7 U3.8 U3.9 U3.10 U3.11 U3.12 U3.13 U3.14 U3.15 U4.1 U4.2 U4.3 U4.4 U4.5 U4.6 U4.7 U4.8 U5.1 U5.2 U5.3 U5.4 U5.5 U5.6 U5.7 U5.8 U6.1 U6.2 U6.3 U6.4 U6.5 U7.1 U7.2 U7.3 U7.4 U7.5 U7.6 U7.7 U7.8 U7.9 U7.10 U7.11 U7.12 U7.13 U7.14 U7.15 U7.16 U7.17 U7.18 U7.19 U7.20 U7.21 U7.22 U7.23 U7.24 U7.25 U7.26 U7.27 U7.28 U7.29 U7.30 U7.31 U7.32 U7.33 U7.34 U7.35 U7.36 U7.37 U7.38 Y1.1 Y1.2 Y1.3 Y2.1 Y2.2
